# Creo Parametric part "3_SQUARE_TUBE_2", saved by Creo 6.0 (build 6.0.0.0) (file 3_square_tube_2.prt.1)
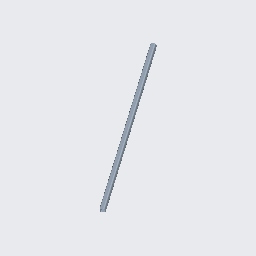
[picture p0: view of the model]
Units: Custom; MM, KILOGRAM, SECS
Materials in the file: STEEL

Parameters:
  BUW_NAME = "SQUARE TUBE"
  BUW_TYPE = "DIN EN 10219"
  BUW_SIZE = "25x25x3.0"
  BUW_LENGTH_STR = "910"
  PTC_MATERIAL_NAME = "STEEL"
  BUW_PROFIL_TYPE = "square_tube"
  BUW_PROFILE_PATH = "parts//profiles/steel_beams_mm/"
  BUW_PROFILE_NAME_LANG = "SQUARE TUBE"
  BUW_TAB_SEL_INFO = "-2 TYPE DIN_EN_10219-1997 SIZE_DINEN_10219 25x25x3.0"
  NAMING = "SQUARE TUBE"
  DESIGNATION = "DIN EN 10219 25x25x3.0 x 910"
  PROFIL_RASTER_POS = "X_0"
  BUW_OBJECT_ROLE = "PROFIL_SYSTEM_BORE_END_POINTS"
  PRO_UNIT_SYS = "Custom"

Other parameters: BUW_LENGTH, LENGTH, BUW_LENGTH_Z_MIN_PARAM, D8, D93, D94, d26, d8, d93, d94, d98, D98, SHEAR_MODULUS, THERM_EXPANSION_REF_TEMPERATURE, STRUCTURAL_DAMPING_COEFFICIENT, STRESS_LIMIT_FOR_TENSION, STRESS_LIMIT_FOR_COMPRESSION, STRESS_LIMIT_FOR_SHEAR, EMISSIVITY

Created from: SQUARE_TUBE.PRT

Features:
  1. datum plane "YZ"
  2. datum plane "XZ"
  3. datum plane "XY"
  4. coordinate system
  5. coordinate system
  6. coordinate system
  7. coordinate system
  8. datum plane "DTM3"
  9. datum plane "DTM4"
  10. datum plane "DTM5"
  11. protrusion
  12. round
  13. round
  14. datum axis
  15. datum point "PNT0"
  16. datum point

Other named items: PROFIL_CUT_QUILT, PROFILE_LENGTH_DIM, CONTACT_SURF_3, CONTACT_SURF_2, CONTACT_SURF_1, CONTACT_SURF_0, E, START_SURFACE, END_SURFACE, SIDE_SURF_3, SIDE_SURF_0, SIDE_SURF_1, SIDE_SURF_2, EDGE_7_S, EDGE_7_E, EDGE_1_S, EDGE_1_E, EDGE_3_S, EDGE_3_E, EDGE_5_S, EDGE_5_E, EDGE_6_S, EDGE_4_S, EDGE_2_S, EDGE_0_S, EDGE_6_E, EDGE_4_E, EDGE_2_E, EDGE_0_E, CS0, CS_S, CS_E, CS3

Named dimensions: X_ROT_S, Y_ROT_S, Z_OFF_S, X_ROT_E, Y_ROT_E, Z_OFF_E, PC_L, BUW_LENGTH_Z_MIN, BUW_LENGTH_DIM

Layers: 00_PROFIL_DATUM, 00_PROFIL_DRW_HIDE, 00_PROFIL_END_CSYS, 00_PROFIL_GEOMETRY, 00_PROFIL_QUILT, 00_PROFIL_SIZE_NOTE

Surfaces: 16 plane, 12 cylinder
